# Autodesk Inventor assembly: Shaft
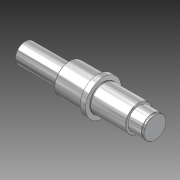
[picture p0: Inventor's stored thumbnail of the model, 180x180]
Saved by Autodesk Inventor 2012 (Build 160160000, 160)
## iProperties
Created: 2007-07
Part Number: Shaft
Document SubType Name: Assembly
Designer: Designer
ClientObjectVersion: 1
Author: Designer
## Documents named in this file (2)
- C:\CMU\Datasets\Session 6\Cluster Ex 1\Workspaces\Workspace\GearBox-A\Design Accelerator\Shaft1.iam
- C:\CMU\Datasets\Session 6\Cluster Ex 1\Workspaces\Workspace\GearBox-A\Design Accelerator\Shaft1.ipt
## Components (1 placed, 1 different names)
1. Shaft:1
